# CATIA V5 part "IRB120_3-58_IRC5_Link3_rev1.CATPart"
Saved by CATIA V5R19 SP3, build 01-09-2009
Part number: Link3
Revision: ANY
Definition: UNKNOWN
Nomenclature: Link3
Source: Unknown
Bounding box of the stored display mesh (mm): x -89.413 to 154.6, y -56 to 59.5, z 511.471 to 699.626
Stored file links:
  Z:\Projects\ABB_Robotics\ABB LIB\V5\V5PARTS\ABB\120\IRB120_3-58_IRC5_Link3_rev1.CATPart
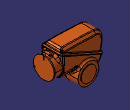
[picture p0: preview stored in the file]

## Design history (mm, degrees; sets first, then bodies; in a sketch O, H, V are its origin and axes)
Body1 "NONE" (main body)
  Solid1: solid without history
Body2 "NONE"
  Solid2: solid without history
Body3 "NONE"
  Solid3: solid without history
Body4 "NONE"
  Solid4: solid without history
Body5 "NONE"
  Solid5: solid without history
Body6 "NONE"
  Solid6: solid without history
Body7 "NONE"
  Solid7: solid without history
Body8 "NONE"
  Solid8: solid without history
Body9 "NONE"
  Solid9: solid without history
Body10 "NONE"
  Solid10: solid without history
Body11 "NONE"
  Solid11: solid without history
Body12 "NONE"
  Solid12: solid without history
Body13 "NONE"
  Solid13: solid without history
Body14 "NONE"
  Solid14: solid without history
Body15 "NONE"
  Solid15: solid without history
Body16 "NONE"
  Solid16: solid without history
